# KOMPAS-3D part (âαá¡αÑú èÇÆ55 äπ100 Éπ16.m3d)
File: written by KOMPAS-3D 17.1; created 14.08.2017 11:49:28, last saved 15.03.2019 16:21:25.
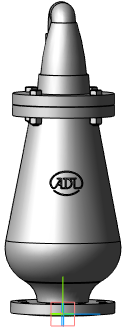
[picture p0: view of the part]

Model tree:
1. Операция без истории:2  (labels: Сталь 20  ГОСТ 1050-2013)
